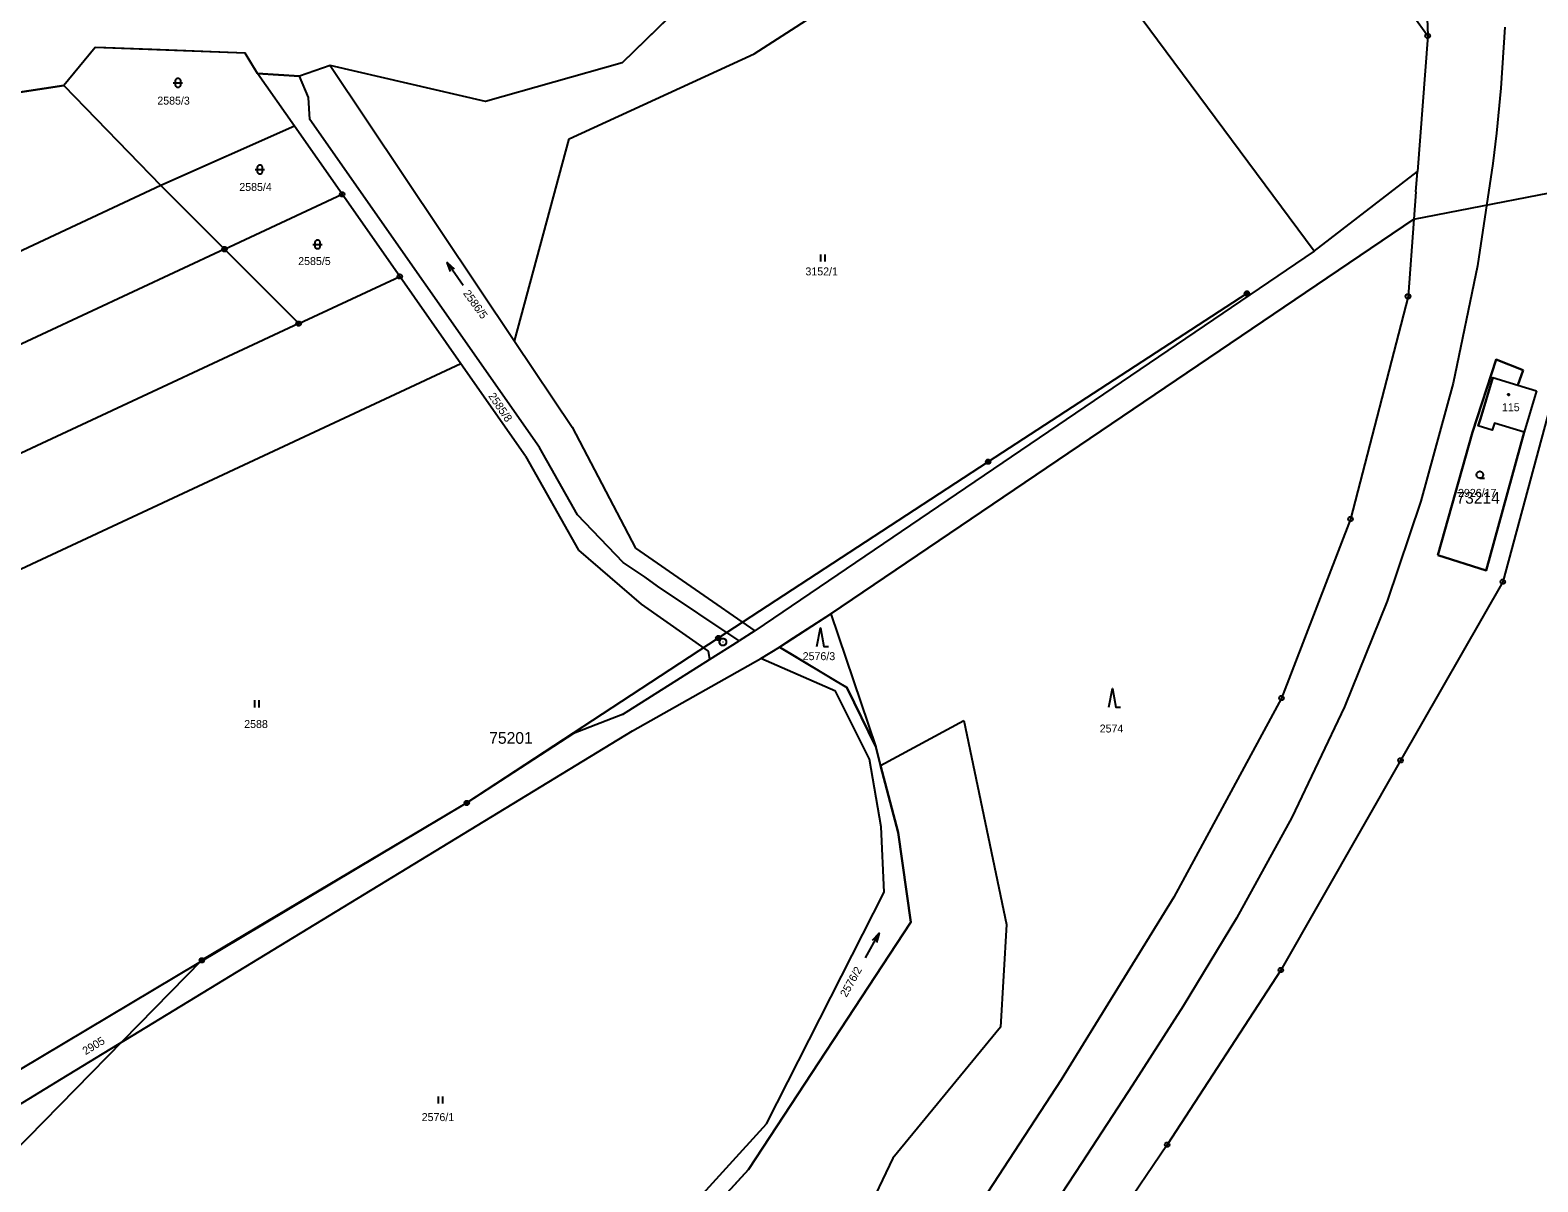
# Model space of a CAD drawing. Extents: x -760611 to -758411, y -1176479 to -1174807.
# Drawn here: x -759798.8 to -759476.2, y -1175989.4 to -1175743.1 of the extents above; entities that cross this region are included whole.
import ezdxf

# ---------------------------------------------------------------- set-up
doc = ezdxf.new("R2010")
doc.units = 0
for name, color, linetype in [('1', 7, 'Continuous'), ('11', 7, 'Continuous'), ('12', 7, 'Continuous'), ('2', 7, 'Continuous'), ('3', 7, 'Continuous'), ('5', 7, 'Continuous'), ('6', 7, 'Continuous'), ('8', 7, 'Continuous')]:
    doc.layers.add(name, color=color, linetype=linetype)

msp = doc.modelspace()

# ---------------------------------------------------------------- linework, layer by layer
at = {"layer": '1'}
for p, q in [((-759524.09, -1175790.32), (-759590.47, -1175700.96)), ((-759643.9, -1175748.13), (-759594.21, -1175716.13)), ((-759646.53, -1175725.11), (-759672.08, -1175750.06)), ((-759500.08, -1175736.74), (-759499.79, -1175744.32)), ((-759502.97, -1175739.86), (-759499.79, -1175744.32)), ((-759499.79, -1175744.32), (-759501.98, -1175773.34)), ((-759784.82, -1175746.79), (-759791.53, -1175754.92)), ((-759752.79, -1175748), (-759784.82, -1175746.79)), ((-759750.12, -1175752.35), (-759752.79, -1175748)), ((-759734.6, -1175750.62), (-759741.17, -1175752.92)), ((-759701.35, -1175758.35), (-759734.6, -1175750.62)), ((-759734.6, -1175750.62), (-759695.17, -1175809.57)), ((-759672.08, -1175750.06), (-759701.35, -1175758.35)), ((-759683.43, -1175766.3), (-759643.9, -1175748.13)), ((-759750.12, -1175752.35), (-759741.17, -1175752.92)), ((-759742.22, -1175763.61), (-759750.12, -1175752.35)), ((-759739.25, -1175757.49), (-759741.17, -1175752.92)), ((-759851.02, -1175763.95), (-759791.53, -1175754.92)), ((-759791.53, -1175754.92), (-759770.79, -1175776.31)), ((-759738.96, -1175762.16), (-759739.25, -1175757.49)), ((-759742.22, -1175763.61), (-759770.79, -1175776.31)), ((-759732.01, -1175778.18), (-759742.22, -1175763.61)), ((-759689.79, -1175832.32), (-759738.96, -1175762.16)), ((-759695.17, -1175809.57), (-759683.43, -1175766.3)), ((-759524.09, -1175790.32), (-759501.98, -1175773.34)), ((-759502.31, -1175777.67), (-759501.98, -1175773.34)), ((-759770.79, -1175776.31), (-759950.87, -1175860.33)), ((-759757.19, -1175789.93), (-759770.79, -1175776.31)), ((-759757.19, -1175789.93), (-759732.01, -1175778.18)), ((-759719.7, -1175795.75), (-759732.01, -1175778.18)), ((-759502.31, -1175777.67), (-759502.75, -1175783.52)), ((-759502.75, -1175783.52), (-759627.47, -1175867.91)), ((-759502.75, -1175783.52), (-759504, -1175800.02)), ((-759757.19, -1175789.93), (-759850.77, -1175833.59)), ((-759741.31, -1175805.84), (-759757.19, -1175789.93)), ((-759524.09, -1175790.32), (-759643.71, -1175871.53)), ((-759741.31, -1175805.84), (-759719.7, -1175795.75)), ((-759706.61, -1175814.43), (-759719.7, -1175795.75)), ((-759504, -1175800.02), (-759516.31, -1175847.66)), ((-759741.31, -1175805.84), (-759839.07, -1175851.45)), ((-759468.84, -1175805.79), (-759483.74, -1175861.06)), ((-759695.17, -1175809.57), (-759682.83, -1175828.02)), ((-759706.61, -1175814.43), (-759817.66, -1175866.24)), ((-759692.76, -1175834.18), (-759706.61, -1175814.43)), ((-759490.2, -1175829.08), (-759485.15, -1175813.53)), ((-759485.15, -1175813.53), (-759479.37, -1175815.8)), ((-759485.87, -1175817.4), (-759488.52, -1175826.24)), ((-759485.87, -1175817.4), (-759480.52, -1175819.01)), ((-759479.37, -1175815.8), (-759480.52, -1175819.01)), ((-759480.52, -1175819.01), (-759476.5, -1175820.22)), ((-759476.5, -1175820.22), (-759479.14, -1175829.06)), ((-759682.83, -1175828.02), (-759669.28, -1175853.85)), ((-759488.52, -1175826.24), (-759488.97, -1175827.71)), ((-759485.97, -1175828.61), (-759488.97, -1175827.71)), ((-759485.53, -1175827.14), (-759485.97, -1175828.61)), ((-759479.14, -1175829.06), (-759485.53, -1175827.14)), ((-759497.6, -1175855.39), (-759490.2, -1175829.08)), ((-759479.14, -1175829.06), (-759487.28, -1175858.65)), ((-759692.76, -1175834.18), (-759681.43, -1175854.32)), ((-759681.7, -1175846.7), (-759689.79, -1175832.32)), ((-759671.92, -1175856.94), (-759681.7, -1175846.7)), ((-759516.31, -1175847.66), (-759531.08, -1175885.93)), ((-759669.28, -1175853.85), (-759643.71, -1175871.53)), ((-759681.43, -1175854.32), (-759668.05, -1175865.81)), ((-759667.23, -1175860.03), (-759671.92, -1175856.94)), ((-759487.28, -1175858.65), (-759497.6, -1175855.39)), ((-759664.54, -1175861.98), (-759667.23, -1175860.03)), ((-759647.08, -1175873.67), (-759664.54, -1175861.98)), ((-759483.74, -1175861.06), (-759505.58, -1175899.24)), ((-759668.05, -1175865.81), (-759653.73, -1175875.86)), ((-759638.48, -1175875), (-759627.47, -1175867.91)), ((-759627.47, -1175867.91), (-759617.87, -1175896.37)), ((-759643.71, -1175871.53), (-759647.08, -1175873.67)), ((-759653.73, -1175875.86), (-759653.45, -1175877.7)), ((-759653.45, -1175877.7), (-759647.08, -1175873.67)), ((-759642.48, -1175877.46), (-759638.48, -1175875)), ((-759638.48, -1175875), (-759624.08, -1175883.65)), ((-759672.04, -1175889.46), (-759653.45, -1175877.7)), ((-759669.89, -1175892.93), (-759642.48, -1175877.46)), ((-759626.47, -1175884.46), (-759642.48, -1175877.46)), ((-759619.21, -1175899.01), (-759626.47, -1175884.46)), ((-759624.08, -1175883.65), (-759617.87, -1175896.37)), ((-759531.08, -1175885.93), (-759554.12, -1175928.53)), ((-759672.04, -1175889.46), (-759682.53, -1175893.46)), ((-759616.82, -1175900.35), (-759599.02, -1175890.68)), ((-759599.02, -1175890.68), (-759589.88, -1175934.33)), ((-759792.04, -1175967.36), (-759669.89, -1175892.93)), ((-759682.53, -1175893.46), (-759705.37, -1175908.34)), ((-759616.68, -1175913.44), (-759619.21, -1175899.01)), ((-759617.87, -1175896.37), (-759616.82, -1175900.35)), ((-759616.82, -1175900.35), (-759613.04, -1175914.7)), ((-759505.58, -1175899.24), (-759531.21, -1175944.09)), ((-759705.37, -1175908.34), (-759821.65, -1175977.68)), ((-759616.04, -1175927.41), (-759616.68, -1175913.44)), ((-759613.04, -1175914.7), (-759610.38, -1175933.87)), ((-759641.25, -1175976.94), (-759616.04, -1175927.41)), ((-759554.12, -1175928.53), (-759578.18, -1175967.56)), ((-759610.38, -1175933.87), (-759645.08, -1175986.7)), ((-759589.88, -1175934.33), (-759591.21, -1175956.3)), ((-759531.21, -1175944.09), (-759555.51, -1175981.46)), ((-759591.21, -1175956.3), (-759614.19, -1175984.28)), ((-759826.71, -1175988.48), (-759792.04, -1175967.36)), ((-759578.18, -1175967.56), (-759605.19, -1176008.78)), ((-759660.74, -1175998.38), (-759641.25, -1175976.94)), ((-759555.51, -1175981.46), (-759583.34, -1176022.38)), ((-759614.19, -1175984.28), (-759620.96, -1175998.45)), ((-759645.08, -1175986.7), (-759664.29, -1176007.68))]:
    msp.add_line(p, q, dxfattribs=at)
at = {"layer": '11'}
for points in [[(-759646.53, -1175725.11), (-759672.08, -1175750.06), (-759701.35, -1175758.35), (-759734.6, -1175750.62), (-759741.17, -1175752.92), (-759750.12, -1175752.35), (-759750.91, -1175751.06), (-759751.68, -1175749.81), (-759752.79, -1175748), (-759772.73, -1175747.25), (-759782.59, -1175746.87), (-759784.82, -1175746.79), (-759785.2, -1175747.25), (-759791.53, -1175754.92), (-759851.02, -1175763.95), (-759853.64, -1175745.06), (-759866.1, -1175736.93)], [(-759814.38, -1176046.99), (-759794.18, -1176050.97), (-759753.8, -1176063.91), (-759750.6, -1176065.19), (-759724.36, -1176074.33), (-759709.52, -1176046.31), (-759667.97, -1176005.44), (-759664.29, -1176007.68), (-759645.08, -1175986.7), (-759610.38, -1175933.87), (-759613.04, -1175914.7), (-759616.82, -1175900.35), (-759617.87, -1175896.37), (-759624.08, -1175883.65), (-759626.24, -1175882.35), (-759636, -1175876.49), (-759638.48, -1175875), (-759636.48, -1175873.71), (-759627.47, -1175867.91), (-759502.75, -1175783.52), (-759461.61, -1175775.54)], [(-759479.37, -1175815.8), (-759485.15, -1175813.53), (-759490.2, -1175829.08), (-759497.6, -1175855.39)], [(-759497.6, -1175855.39), (-759487.28, -1175858.65), (-759479.14, -1175829.06), (-759485.53, -1175827.14), (-759485.97, -1175828.61), (-759488.97, -1175827.71), (-759488.52, -1175826.24), (-759485.87, -1175817.4), (-759480.52, -1175819.01), (-759479.37, -1175815.8)]]:
    msp.add_lwpolyline(points, dxfattribs=at)
at = {"layer": '12'}
for p, q in [((-759485.87, -1175817.4), (-759488.52, -1175826.24)), ((-759485.87, -1175817.4), (-759480.52, -1175819.01)), ((-759480.52, -1175819.01), (-759476.5, -1175820.22)), ((-759476.5, -1175820.22), (-759479.14, -1175829.06)), ((-759488.52, -1175826.24), (-759488.97, -1175827.71)), ((-759485.97, -1175828.61), (-759488.97, -1175827.71)), ((-759485.53, -1175827.14), (-759485.97, -1175828.61)), ((-759479.14, -1175829.06), (-759485.53, -1175827.14))]:
    msp.add_line(p, q, dxfattribs=at)
at = {"layer": '3'}
for p, q in [((-759706.14, -1175797.69), (-759709.58, -1175792.77)), ((-759629.7, -1175791.07), (-759629.7, -1175792.57)), ((-759628.7, -1175792.57), (-759628.7, -1175791.07)), ((-759750.78, -1175886.4), (-759750.78, -1175887.9)), ((-759749.78, -1175887.9), (-759749.78, -1175886.4)), ((-759620.08, -1175941.45), (-759617.14, -1175936.21)), ((-759711.48, -1175971.1), (-759711.48, -1175972.6)), ((-759710.48, -1175972.6), (-759710.48, -1175971.1))]:
    msp.add_line(p, q, dxfattribs=at)
for points in [[(-759767.64, -1175753.86), (-759767.54, -1175753.57), (-759767.29, -1175753.39), (-759766.98, -1175753.39), (-759766.73, -1175753.57), (-759766.63, -1175753.86), (-759766.63, -1175754.86), (-759766.73, -1175755.15), (-759766.98, -1175755.33), (-759767.29, -1175755.33), (-759767.54, -1175755.15), (-759767.64, -1175754.86)], [(-759750.11, -1175772.38), (-759750.01, -1175772.09), (-759749.76, -1175771.91), (-759749.45, -1175771.91), (-759749.2, -1175772.09), (-759749.1, -1175772.38), (-759749.1, -1175773.38), (-759749.2, -1175773.67), (-759749.45, -1175773.85), (-759749.76, -1175773.85), (-759750.01, -1175773.67), (-759750.11, -1175773.38)], [(-759737.77, -1175788.4), (-759737.67, -1175788.11), (-759737.42, -1175787.93), (-759737.11, -1175787.93), (-759736.86, -1175788.11), (-759736.76, -1175788.4), (-759736.76, -1175789.4), (-759736.86, -1175789.69), (-759737.11, -1175789.87), (-759737.42, -1175789.87), (-759737.67, -1175789.69), (-759737.77, -1175789.4)]]:
    msp.add_lwpolyline(points, close=True, dxfattribs=at)
for points in [[(-759768.14, -1175754.36), (-759766.87, -1175754.36), (-759766.14, -1175754.36)], [(-759750.61, -1175772.88), (-759749.34, -1175772.88), (-759748.61, -1175772.88)], [(-759738.27, -1175788.9), (-759737, -1175788.9), (-759736.27, -1175788.9)], [(-759708.84, -1175794.7), (-759709.58, -1175792.77), (-759708.02, -1175794.12)], [(-759488.63, -1175838.9), (-759489.01, -1175838.8), (-759489.28, -1175838.53), (-759489.38, -1175838.16), (-759489.28, -1175837.79), (-759489.01, -1175837.52), (-759488.64, -1175837.42), (-759488.27, -1175837.52), (-759488, -1175837.79), (-759487.9, -1175838.17), (-759488, -1175838.55), (-759488.27, -1175838.82), (-759488.65, -1175838.92), (-759487.65, -1175838.92)], [(-759630.45, -1175874.88), (-759629.7, -1175870.88), (-759628.95, -1175874.88), (-759627.95, -1175874.88)], [(-759567.99, -1175887.88), (-759567.24, -1175883.88), (-759566.49, -1175887.88), (-759565.49, -1175887.88)], [(-759618.56, -1175937.71), (-759617.14, -1175936.21), (-759617.68, -1175938.2)]]:
    msp.add_lwpolyline(points, dxfattribs=at)
at = {"layer": '5'}
msp.add_lwpolyline([(-759482.51, -1175820.85), (-759482.41, -1175820.87), (-759482.36, -1175820.96), (-759482.34, -1175821.02), (-759482.36, -1175821.11), (-759482.44, -1175821.18), (-759482.51, -1175821.19), (-759482.6, -1175821.16), (-759482.66, -1175821.1), (-759482.68, -1175821.02), (-759482.66, -1175820.93), (-759482.58, -1175820.86)], close=True, dxfattribs=at)
at = {"layer": '6'}
for p, q in [((-759483.28, -1175742.43), (-759484.17, -1175755.51)), ((-759484.17, -1175755.51), (-759485.08, -1175765.13)), ((-759485.08, -1175765.13), (-759485.84, -1175771.58)), ((-759485.84, -1175771.58), (-759489.12, -1175793.5)), ((-759489.12, -1175793.5), (-759494.33, -1175818.57)), ((-759538.46, -1175799.41), (-759593.85, -1175835.4)), ((-759494.33, -1175818.57), (-759501.23, -1175843.78)), ((-759593.85, -1175835.4), (-759651.57, -1175873.1)), ((-759501.23, -1175843.78), (-759508.46, -1175865.17)), ((-759508.46, -1175865.17), (-759517.58, -1175887.77)), ((-759651.57, -1175873.1), (-759705.37, -1175908.34)), ((-759517.58, -1175887.77), (-759528.87, -1175911.44)), ((-759705.37, -1175908.34), (-759762.02, -1175941.99)), ((-759528.87, -1175911.44), (-759540.69, -1175932.95)), ((-759540.69, -1175932.95), (-759552.11, -1175951.77)), ((-759762.02, -1175941.99), (-759807.85, -1175988.69)), ((-759552.11, -1175951.77), (-759562.93, -1175968.72)), ((-759562.93, -1175968.72), (-759573.8, -1175985.33)), ((-759573.8, -1175985.33), (-759600.99, -1176026.52))]:
    msp.add_line(p, q, dxfattribs=at)
for points in [[(-759538.61, -1175798.93), (-759538.3, -1175798.93), (-759538.05, -1175799.11), (-759537.95, -1175799.4), (-759538.05, -1175799.69), (-759538.3, -1175799.87), (-759538.61, -1175799.87), (-759538.86, -1175799.69), (-759538.96, -1175799.4), (-759538.86, -1175799.11), (-759538.61, -1175798.93), (-759538.58, -1175798.97), (-759538.34, -1175798.97), (-759538.18, -1175799.05), (-759538.74, -1175799.05), (-759538.82, -1175799.13), (-759538.1, -1175799.13), (-759538.1, -1175799.21), (-759538.82, -1175799.21), (-759538.86, -1175799.29), (-759538.06, -1175799.29), (-759538.02, -1175799.37), (-759538.9, -1175799.37), (-759538.9, -1175799.45), (-759538.02, -1175799.45), (-759538.05, -1175799.53), (-759538.86, -1175799.53), (-759538.85, -1175799.61), (-759538.04, -1175799.61), (-759538.09, -1175799.69), (-759538.81, -1175799.69), (-759538.73, -1175799.77), (-759538.17, -1175799.77), (-759538.28, -1175799.85), (-759538.62, -1175799.85)], [(-759594, -1175834.92), (-759593.69, -1175834.92), (-759593.44, -1175835.1), (-759593.34, -1175835.39), (-759593.44, -1175835.68), (-759593.69, -1175835.86), (-759594, -1175835.86), (-759594.25, -1175835.68), (-759594.35, -1175835.39), (-759594.25, -1175835.1), (-759594, -1175834.92), (-759593.97, -1175834.96), (-759593.73, -1175834.96), (-759593.57, -1175835.04), (-759594.13, -1175835.04), (-759594.21, -1175835.12), (-759593.49, -1175835.12), (-759593.49, -1175835.2), (-759594.21, -1175835.2), (-759594.25, -1175835.28), (-759593.45, -1175835.28), (-759593.41, -1175835.36), (-759594.29, -1175835.36), (-759594.29, -1175835.44), (-759593.41, -1175835.44), (-759593.44, -1175835.52), (-759594.25, -1175835.52), (-759594.24, -1175835.6), (-759593.43, -1175835.6), (-759593.48, -1175835.68), (-759594.2, -1175835.68), (-759594.12, -1175835.76), (-759593.56, -1175835.76), (-759593.67, -1175835.84), (-759594.01, -1175835.84)], [(-759651.72, -1175872.62), (-759651.41, -1175872.62), (-759651.16, -1175872.8), (-759651.06, -1175873.09), (-759651.16, -1175873.38), (-759651.41, -1175873.56), (-759651.72, -1175873.56), (-759651.97, -1175873.38), (-759652.07, -1175873.09), (-759651.97, -1175872.8), (-759651.72, -1175872.62), (-759651.69, -1175872.66), (-759651.45, -1175872.66), (-759651.29, -1175872.74), (-759651.85, -1175872.74), (-759651.93, -1175872.82), (-759651.21, -1175872.82), (-759651.21, -1175872.9), (-759651.93, -1175872.9), (-759651.97, -1175872.98), (-759651.17, -1175872.98), (-759651.13, -1175873.06), (-759652.01, -1175873.06), (-759652.01, -1175873.14), (-759651.13, -1175873.14), (-759651.16, -1175873.22), (-759651.97, -1175873.22), (-759651.96, -1175873.3), (-759651.15, -1175873.3), (-759651.2, -1175873.38), (-759651.92, -1175873.38), (-759651.84, -1175873.46), (-759651.28, -1175873.46), (-759651.39, -1175873.54), (-759651.73, -1175873.54)], [(-759705.52, -1175907.86), (-759705.21, -1175907.86), (-759704.96, -1175908.04), (-759704.86, -1175908.33), (-759704.96, -1175908.62), (-759705.21, -1175908.8), (-759705.52, -1175908.8), (-759705.77, -1175908.62), (-759705.87, -1175908.33), (-759705.77, -1175908.04), (-759705.52, -1175907.86), (-759705.49, -1175907.9), (-759705.25, -1175907.9), (-759705.09, -1175907.98), (-759705.65, -1175907.98), (-759705.73, -1175908.06), (-759705.01, -1175908.06), (-759705.01, -1175908.14), (-759705.73, -1175908.14), (-759705.77, -1175908.22), (-759704.97, -1175908.22), (-759704.93, -1175908.3), (-759705.81, -1175908.3), (-759705.81, -1175908.38), (-759704.93, -1175908.38), (-759704.96, -1175908.46), (-759705.77, -1175908.46), (-759705.76, -1175908.54), (-759704.95, -1175908.54), (-759705, -1175908.62), (-759705.72, -1175908.62), (-759705.64, -1175908.7), (-759705.08, -1175908.7), (-759705.19, -1175908.78), (-759705.53, -1175908.78)], [(-759762.17, -1175941.51), (-759761.86, -1175941.51), (-759761.61, -1175941.69), (-759761.51, -1175941.98), (-759761.61, -1175942.27), (-759761.86, -1175942.45), (-759762.17, -1175942.45), (-759762.42, -1175942.27), (-759762.52, -1175941.98), (-759762.42, -1175941.69), (-759762.17, -1175941.51), (-759762.14, -1175941.55), (-759761.9, -1175941.55), (-759761.74, -1175941.63), (-759762.3, -1175941.63), (-759762.38, -1175941.71), (-759761.66, -1175941.71), (-759761.66, -1175941.79), (-759762.38, -1175941.79), (-759762.42, -1175941.87), (-759761.62, -1175941.87), (-759761.58, -1175941.95), (-759762.46, -1175941.95), (-759762.46, -1175942.03), (-759761.58, -1175942.03), (-759761.61, -1175942.11), (-759762.42, -1175942.11), (-759762.41, -1175942.19), (-759761.6, -1175942.19), (-759761.65, -1175942.27), (-759762.37, -1175942.27), (-759762.29, -1175942.35), (-759761.73, -1175942.35), (-759761.84, -1175942.43), (-759762.18, -1175942.43)]]:
    msp.add_lwpolyline(points, dxfattribs=at)
at = {"layer": '8'}
for p, q in [((-759499.91, -1175744.32), (-759499.67, -1175744.32)), ((-759732.13, -1175778.18), (-759731.89, -1175778.18)), ((-759757.31, -1175789.93), (-759757.07, -1175789.93)), ((-759719.82, -1175795.75), (-759719.58, -1175795.75)), ((-759504.12, -1175800.02), (-759503.88, -1175800.02)), ((-759741.43, -1175805.84), (-759741.19, -1175805.84)), ((-759516.43, -1175847.66), (-759516.19, -1175847.66)), ((-759483.86, -1175861.06), (-759483.62, -1175861.06)), ((-759650.61, -1175873.92), (-759650.51, -1175873.92)), ((-759531.2, -1175885.93), (-759530.96, -1175885.93)), ((-759505.7, -1175899.24), (-759505.46, -1175899.24)), ((-759531.33, -1175944.09), (-759531.09, -1175944.09)), ((-759555.63, -1175981.46), (-759555.39, -1175981.46))]:
    msp.add_line(p, q, dxfattribs=at)
for points in [[(-759499.64, -1175743.84), (-759499.39, -1175744.02), (-759499.29, -1175744.31), (-759499.39, -1175744.6), (-759499.64, -1175744.78), (-759499.95, -1175744.78), (-759500.2, -1175744.6), (-759500.3, -1175744.31), (-759500.2, -1175744.02), (-759499.95, -1175743.84)], [(-759731.86, -1175777.7), (-759731.61, -1175777.88), (-759731.51, -1175778.17), (-759731.61, -1175778.46), (-759731.86, -1175778.64), (-759732.17, -1175778.64), (-759732.42, -1175778.46), (-759732.52, -1175778.17), (-759732.42, -1175777.88), (-759732.17, -1175777.7)], [(-759757.04, -1175789.45), (-759756.79, -1175789.63), (-759756.69, -1175789.92), (-759756.79, -1175790.21), (-759757.04, -1175790.39), (-759757.35, -1175790.39), (-759757.6, -1175790.21), (-759757.7, -1175789.92), (-759757.6, -1175789.63), (-759757.35, -1175789.45)], [(-759719.55, -1175795.27), (-759719.3, -1175795.45), (-759719.2, -1175795.74), (-759719.3, -1175796.03), (-759719.55, -1175796.21), (-759719.86, -1175796.21), (-759720.11, -1175796.03), (-759720.21, -1175795.74), (-759720.11, -1175795.45), (-759719.86, -1175795.27)], [(-759503.85, -1175799.54), (-759503.6, -1175799.72), (-759503.5, -1175800.01), (-759503.6, -1175800.3), (-759503.85, -1175800.48), (-759504.16, -1175800.48), (-759504.41, -1175800.3), (-759504.51, -1175800.01), (-759504.41, -1175799.72), (-759504.16, -1175799.54)], [(-759741.16, -1175805.36), (-759740.91, -1175805.54), (-759740.81, -1175805.83), (-759740.91, -1175806.12), (-759741.16, -1175806.3), (-759741.47, -1175806.3), (-759741.72, -1175806.12), (-759741.82, -1175805.83), (-759741.72, -1175805.54), (-759741.47, -1175805.36)], [(-759516.16, -1175847.18), (-759515.91, -1175847.36), (-759515.81, -1175847.65), (-759515.91, -1175847.94), (-759516.16, -1175848.12), (-759516.47, -1175848.12), (-759516.72, -1175847.94), (-759516.82, -1175847.65), (-759516.72, -1175847.36), (-759516.47, -1175847.18)], [(-759483.59, -1175860.58), (-759483.34, -1175860.76), (-759483.24, -1175861.05), (-759483.34, -1175861.34), (-759483.59, -1175861.52), (-759483.9, -1175861.52), (-759484.15, -1175861.34), (-759484.25, -1175861.05), (-759484.15, -1175860.76), (-759483.9, -1175860.58)], [(-759650.37, -1175873.2), (-759650.03, -1175873.39), (-759649.84, -1175873.73), (-759649.84, -1175874.12), (-759650.03, -1175874.46), (-759650.37, -1175874.65), (-759650.76, -1175874.65), (-759651.1, -1175874.46), (-759651.29, -1175874.12), (-759651.29, -1175873.73), (-759651.1, -1175873.39), (-759650.76, -1175873.2)], [(-759530.93, -1175885.45), (-759530.68, -1175885.63), (-759530.58, -1175885.92), (-759530.68, -1175886.21), (-759530.93, -1175886.39), (-759531.24, -1175886.39), (-759531.49, -1175886.21), (-759531.59, -1175885.92), (-759531.49, -1175885.63), (-759531.24, -1175885.45)], [(-759505.43, -1175898.76), (-759505.18, -1175898.94), (-759505.08, -1175899.23), (-759505.18, -1175899.52), (-759505.43, -1175899.7), (-759505.74, -1175899.7), (-759505.99, -1175899.52), (-759506.09, -1175899.23), (-759505.99, -1175898.94), (-759505.74, -1175898.76)], [(-759531.06, -1175943.61), (-759530.81, -1175943.79), (-759530.71, -1175944.08), (-759530.81, -1175944.37), (-759531.06, -1175944.55), (-759531.37, -1175944.55), (-759531.62, -1175944.37), (-759531.72, -1175944.08), (-759531.62, -1175943.79), (-759531.37, -1175943.61)], [(-759555.36, -1175980.98), (-759555.11, -1175981.16), (-759555.01, -1175981.45), (-759555.11, -1175981.74), (-759555.36, -1175981.92), (-759555.67, -1175981.92), (-759555.92, -1175981.74), (-759556.02, -1175981.45), (-759555.92, -1175981.16), (-759555.67, -1175980.98)]]:
    msp.add_lwpolyline(points, close=True, dxfattribs=at)

# ---------------------------------------------------------------- texts
at = {"layer": '11'}
for s, p in [('73214', (-759493.65, -1175844.35)), ('75201', (-759700.55, -1175895.69))]:
    msp.add_text(s, height=2.5, dxfattribs=at).set_placement(p)
at = {"layer": '2'}
for s, p in [('2585/3', (-759771.56, -1175759.01)), ('2585/4', (-759754.02, -1175777.47)), ('2585/5', (-759741.42, -1175793.32)), ('3152/1', (-759632.91, -1175795.53)), ('115', (-759483.91, -1175824.58)), ('2926/17', (-759493.31, -1175842.89)), ('2576/3', (-759633.5, -1175877.81)), ('2588', (-759752.97, -1175892.32)), ('2574', (-759569.96, -1175893.28)), ('2576/1', (-759715, -1175976.38))]:
    msp.add_text(s, height=1.7, dxfattribs=at).set_placement(p)
for s, rotation, p in [('2586/5', 305.9022, (-759706.21, -1175799.39)), ('2585/8', 304.2406, (-759700.83, -1175821.32)), ('2576/2', 60.7335, (-759624.14, -1175950.03)), ('2905', 31.2262, (-759786.92, -1175962.3))]:
    msp.add_text(s, height=1.7, rotation=rotation, dxfattribs=at).set_placement(p)

doc.saveas('drawing.dxf')
